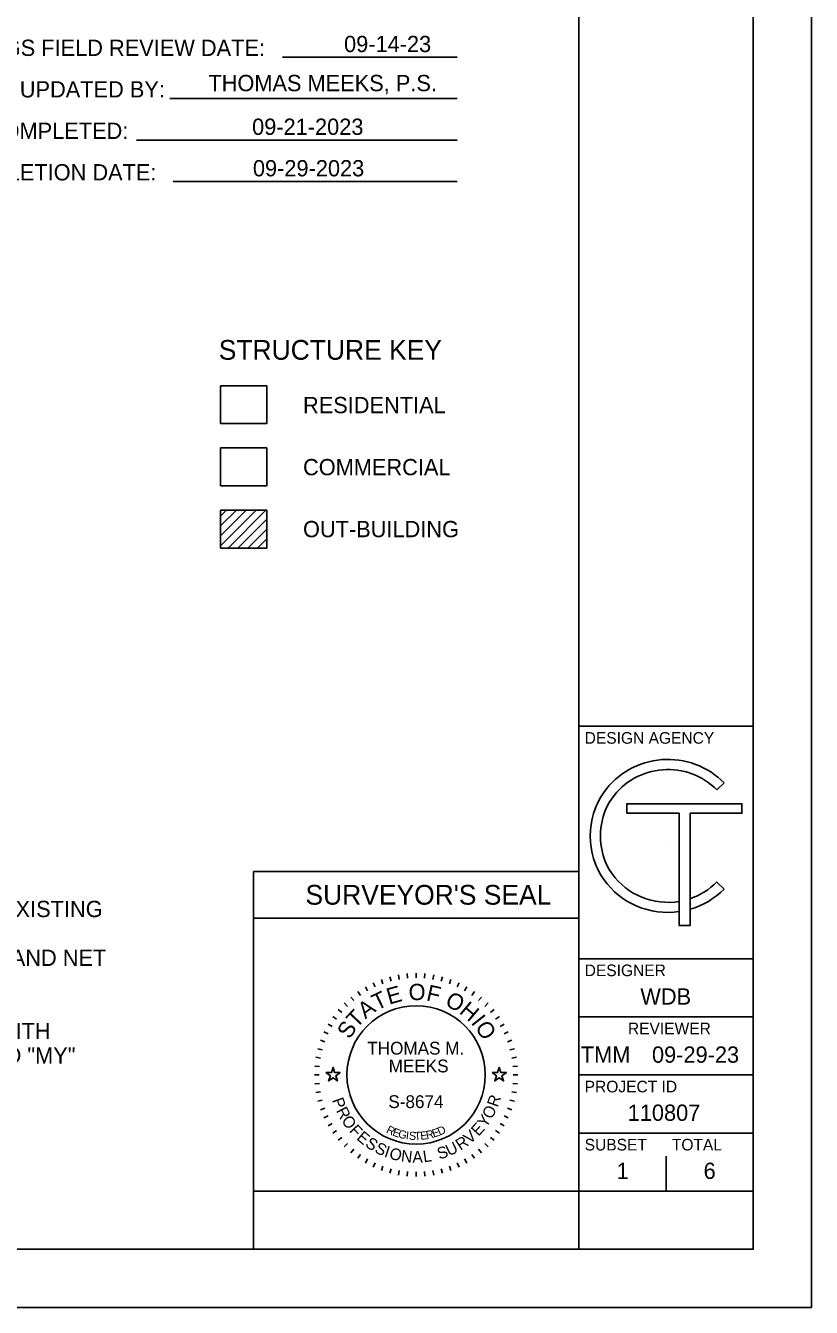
# Model space of a CAD drawing. Extents: x 0 to 34, y 0 to 22.
# Drawn here: x 27.24 to 34, y 0 to 11.03 of the extents above; entities that cross this region are included whole.
import ezdxf

# ---------------------------------------------------------------- set-up
doc = ezdxf.new("R2010")
doc.units = 0
for name, color, linetype in [('Default', 7, 'Continuous'), ('SC_Shading1', 7, 'Continuous'), ('SH_Border', 7, 'Continuous'), ('SH_Cut_Line', 7, 'Continuous'), ('SH_Data', 7, 'Continuous'), ('SH_Text', 7, 'Continuous')]:
    doc.layers.add(name, color=color, linetype=linetype)

msp = doc.modelspace()

# ---------------------------------------------------------------- linework, layer by layer
at = {"layer": 'Default'}
for points in [[(29.824, 2.02), (29.871, 2.02), (29.885, 2.065), (29.899, 2.02), (29.946, 2.02), (29.908, 1.992), (29.923, 1.948), (29.885, 1.975), (29.847, 1.948), (29.862, 1.992)], [(31.254, 2.02), (31.301, 2.02), (31.315, 2.065), (31.329, 2.02), (31.376, 2.02), (31.338, 1.992), (31.353, 1.948), (31.315, 1.975), (31.277, 1.948), (31.292, 1.992)]]:
    msp.add_lwpolyline(points, close=True, dxfattribs=at)
at = {"layer": 'SC_Shading1'}
msp.add_lwpolyline([(28.918, 7.069), (29.315, 7.069), (29.315, 7.395), (28.918, 7.395)], close=True, dxfattribs=at)
at = {"layer": 'SH_Border'}
for p, q in [((32, 0.5), (32, 21.5)), ((32, 5), (33.5, 5)), ((32, 3), (33.5, 3)), ((32, 2.5), (33.5, 2.5)), ((32, 2), (33.5, 2)), ((32, 1.5), (33.5, 1.5)), ((32, 1), (33.5, 1))]:
    msp.add_line(p, q, dxfattribs=at)
msp.add_lwpolyline([(1.5, 21.5), (33.5, 21.5), (33.5, 0.5), (1.5, 0.5)], close=True, dxfattribs=at)
at = {"layer": 'SH_Cut_Line'}
msp.add_lwpolyline([(0, 0), (34, 0), (34, 22), (0, 22)], close=True, dxfattribs=at)
at = {"layer": 'SH_Data'}
for p, q in [((32.75, 4), (32.75, 4)), ((32, 3.75), (29.2, 3.75)), ((29.2, 3.75), (29.2, 0.5)), ((32, 0.5), (32, 3.75)), ((32, 3.35), (29.2, 3.35)), ((30.524, 2.872), (30.527, 2.832)), ((30.6, 2.875), (30.6, 2.835)), ((30.676, 2.872), (30.673, 2.832)), ((30.163, 2.758), (30.183, 2.723)), ((30.23, 2.793), (30.247, 2.757)), ((30.301, 2.822), (30.314, 2.785)), ((30.374, 2.845), (30.384, 2.807)), ((30.448, 2.862), (30.455, 2.822)), ((30.752, 2.862), (30.745, 2.822)), ((30.826, 2.845), (30.816, 2.807)), ((30.899, 2.822), (30.886, 2.785)), ((30.97, 2.793), (30.953, 2.757)), ((31.037, 2.758), (31.017, 2.723)), ((30.038, 2.67), (30.063, 2.64)), ((30.098, 2.717), (30.121, 2.684)), ((31.102, 2.717), (31.079, 2.684)), ((31.162, 2.67), (31.137, 2.64)), ((29.93, 2.562), (29.96, 2.537)), ((29.981, 2.619), (30.01, 2.59)), ((31.219, 2.619), (31.19, 2.59)), ((31.27, 2.562), (31.24, 2.537)), ((29.842, 2.438), (29.877, 2.418)), ((29.883, 2.502), (29.916, 2.479)), ((31.317, 2.502), (31.284, 2.479)), ((31.358, 2.438), (31.323, 2.418)), ((29.807, 2.37), (29.843, 2.353)), ((31.393, 2.37), (31.357, 2.353)), ((29.755, 2.226), (29.793, 2.216)), ((29.778, 2.299), (29.815, 2.286)), ((31.422, 2.299), (31.385, 2.286)), ((31.445, 2.226), (31.407, 2.216)), ((29.738, 2.152), (29.778, 2.145)), ((31.462, 2.152), (31.422, 2.145)), ((29.725, 2), (29.765, 2)), ((29.728, 2.076), (29.768, 2.073)), ((31.472, 2.076), (31.432, 2.073)), ((31.475, 2), (31.435, 2)), ((29.728, 1.924), (29.768, 1.927)), ((31.472, 1.924), (31.432, 1.927)), ((29.738, 1.848), (29.778, 1.855)), ((29.755, 1.774), (29.793, 1.784)), ((31.445, 1.774), (31.407, 1.784)), ((31.462, 1.848), (31.422, 1.855)), ((29.778, 1.701), (29.815, 1.714)), ((31.422, 1.701), (31.385, 1.714)), ((29.807, 1.63), (29.843, 1.647)), ((29.842, 1.563), (29.877, 1.583)), ((31.358, 1.563), (31.323, 1.583)), ((31.393, 1.63), (31.357, 1.647)), ((29.883, 1.498), (29.916, 1.521)), ((29.93, 1.438), (29.96, 1.463)), ((31.27, 1.438), (31.24, 1.463)), ((31.317, 1.498), (31.284, 1.521)), ((29.981, 1.381), (30.01, 1.41)), ((30.038, 1.33), (30.063, 1.36)), ((31.162, 1.33), (31.137, 1.36)), ((31.219, 1.381), (31.19, 1.41)), ((30.098, 1.283), (30.121, 1.316)), ((30.163, 1.242), (30.183, 1.277)), ((30.23, 1.207), (30.247, 1.243)), ((30.301, 1.178), (30.314, 1.215)), ((30.899, 1.178), (30.886, 1.215)), ((30.97, 1.207), (30.953, 1.243)), ((31.037, 1.242), (31.017, 1.277)), ((31.102, 1.283), (31.079, 1.316)), ((32.75, 1), (32.75, 1.3)), ((30.374, 1.155), (30.384, 1.193)), ((30.448, 1.138), (30.455, 1.178)), ((30.524, 1.128), (30.527, 1.168)), ((30.6, 1.125), (30.6, 1.165)), ((30.676, 1.128), (30.673, 1.168)), ((30.752, 1.138), (30.745, 1.178)), ((30.826, 1.155), (30.816, 1.193)), ((32, 0.5), (29.2, 0.5))]:
    msp.add_line(p, q, dxfattribs=at)
msp.add_lwpolyline([(32, 0.5), (32, 1), (29.2, 1), (29.2, 0.5)], close=True, dxfattribs=at)
msp.add_circle((30.6, 2), 0.595, dxfattribs=at)
at = {"layer": 'SH_Text'}
for p, q in [((29.45, 10.758), (30.953, 10.758)), ((28.48, 10.401), (30.953, 10.401)), ((28.195, 10.044), (30.953, 10.044)), ((28.51, 9.687), (30.953, 9.687)), ((28.918, 6.858), (28.919, 6.86)), ((28.918, 6.808), (28.969, 6.86)), ((28.918, 6.724), (29.054, 6.86)), ((28.918, 6.639), (29.138, 6.86)), ((28.918, 6.554), (29.223, 6.86)), ((28.982, 6.534), (29.308, 6.86)), ((29.067, 6.534), (29.315, 6.782)), ((29.151, 6.534), (29.315, 6.697)), ((28.918, 6.538), (28.922, 6.534)), ((29.236, 6.534), (29.315, 6.612)), ((33.249, 4.513), (33.187, 4.452)), ((33.249, 4.513), (33.187, 4.452)), ((33.402, 4.333), (32.414, 4.333)), ((32.414, 4.333), (32.414, 4.251)), ((33.402, 4.251), (33.402, 4.333)), ((32.414, 4.251), (32.863, 4.251)), ((32.863, 4.251), (32.863, 3.285)), ((32.956, 3.285), (32.956, 4.251)), ((32.956, 4.251), (33.402, 4.251)), ((33.187, 3.66), (33.249, 3.599)), ((33.187, 3.66), (33.249, 3.599)), ((32.863, 3.493), (32.863, 3.405)), ((32.863, 3.493), (32.863, 3.405)), ((32.956, 3.425), (32.956, 3.516)), ((32.956, 3.425), (32.956, 3.516)), ((32.863, 3.285), (32.956, 3.285))]:
    msp.add_line(p, q, dxfattribs=at)
for points in [[(28.918, 7.93), (29.315, 7.93), (29.315, 7.605), (28.918, 7.605)], [(28.918, 6.86), (29.315, 6.86), (29.315, 6.534), (28.918, 6.534)], [(32.863, 4.251), (32.863, 3.285), (32.956, 3.285), (32.956, 4.251), (33.402, 4.251), (33.402, 4.333), (32.414, 4.333), (32.414, 4.251)]]:
    msp.add_lwpolyline(points, close=True, dxfattribs=at)
for centre, radius, start, end in [((32.766, 4.035), 0.68, 44.7027, 144.3276), ((32.766, 4.035), 0.68, 44.7027, 144.3276), ((32.766, 4.035), 0.593, 44.7362, 144.1102), ((32.766, 4.035), 0.593, 44.7362, 144.1102), ((32.764, 4.056), 0.666, 145.7329, 214.2671), ((32.764, 4.056), 0.666, 145.7329, 214.2671), ((32.764, 4.056), 0.579, 145.7266, 214.2734), ((32.764, 4.056), 0.579, 145.7266, 214.2734), ((32.766, 4.078), 0.68, 215.6724, 278.2613), ((32.766, 4.078), 0.68, 215.6724, 278.2613), ((32.766, 4.078), 0.593, 215.8898, 279.4882), ((32.766, 4.078), 0.593, 215.8898, 279.4882), ((32.766, 4.078), 0.593, 288.6992, 315.2638), ((32.766, 4.078), 0.593, 288.6992, 315.2638), ((32.766, 4.078), 0.68, 286.2291, 315.2973), ((32.766, 4.078), 0.68, 286.2291, 315.2973)]:
    msp.add_arc(centre, radius, start, end, dxfattribs=at)

# ---------------------------------------------------------------- texts
at = {"layer": 'Default'}
for s, p in [('09-14-23', (29.98, 10.801)), ('THOMAS MEEKS, P.S.', (28.813, 10.465)), ('09-21-2023', (29.189, 10.089)), ('09-29-2023', (29.196, 9.732))]:
    msp.add_text(s, height=0.14, dxfattribs=at).set_placement(p)
at = {"layer": 'SH_Data'}
for s, height, p in [('DESIGN AGENCY', 0.1, (32.05, 4.85)), ("SURVEYOR'S SEAL", 0.17, (29.648, 3.465)), ('I HAVE REESTABLISHED THE LOCATIONS OF THE EXISTING PROPERTY LINES, THE EXISTING CENTERLINE RIGHT OF WAY, AND THE EXISTING', 0.14, (14.869, 3.358)), ('ESTABLISHED THE PROPOSED PROPERTY LINES, CALCULATED THE GROSS TAKE, PRESENT ROADWAY OCCUPIED (PRO), NET TAKE AND NET', 0.14, (14.869, 2.938)), ('DESIGNER', 0.1, (32.05, 2.85)), ('WDB', 0.14, (32.529, 2.605)), ('DEPARTMENT OF TRANSPORTATION DATED 09-22-2010. ALL OF MY WORK CONTAINED HEREIN WAS CONDUCTED IN ACCORDANCE WITH', 0.14, (14.869, 2.308)), ('REVIEWER', 0.1, (32.422, 2.35)), ('THE OHIO ADMINISTRATIVE CODE CHAPTER 4733-37 STANDARDS FOR BOUNDARY SURVEYS, UNLESS SO NOTED. THE WORDS "I" AND "MY"', 0.14, (14.869, 2.098)), ('THOMAS M.', 0.11, (30.18, 2.175)), ('TMM', 0.14, (32.017, 2.105)), ('09-29-23', 0.14, (32.629, 2.105)), ('MEEKS', 0.11, (30.364, 2.022)), ('PROJECT ID', 0.1, (32.05, 1.85)), ('S-8674', 0.11, (30.361, 1.715)), ('110807', 0.14, (32.42, 1.605)), ('SUBSET', 0.1, (32.05, 1.35)), ('TOTAL', 0.1, (32.8, 1.35)), ('1', 0.14, (32.325, 1.105)), ('6', 0.14, (33.073, 1.105))]:
    msp.add_text(s, height=height, dxfattribs=at).set_placement(p)
for s, height, rotation, p in [('E', 0.14, 15.7571, (30.368, 2.604)), ('O', 0.14, 359.7812, (30.535, 2.644)), ('F', 0.14, 347.4362, (30.681, 2.642)), ('T', 0.14, 25.7167, (30.262, 2.552)), ('O', 0.14, 332.2586, (30.84, 2.602)), ('T', 0.14, 46.4344, (30.088, 2.396)), ('A', 0.14, 36.4747, (30.163, 2.478)), ('H', 0.14, 319.9136, (30.963, 2.536)), ('S', 0.14, 57.1924, (30.028, 2.301)), ('I', 0.14, 308.367, (31.066, 2.448)), ('O', 0.14, 303.1491, (31.102, 2.409)), ('P', 0.1, 289.7431, (29.875, 1.784)), ('R', 0.1, 70.983, (31.301, 1.717)), ('R', 0.1, 296.9802, (29.909, 1.693)), ('Y', 0.1, 55.5058, (31.2, 1.54)), ('O', 0.1, 62.7428, (31.25, 1.613)), ('O', 0.1, 304.7158, (29.953, 1.608)), ('F', 0.1, 312.956, (30.019, 1.516)), ('R', 0.07, 334.487, (30.337, 1.505)), ('D', 0.07, 23.3052, (30.801, 1.477)), ('E', 0.1, 48.2687, (31.137, 1.467)), ('E', 0.1, 319.6885, (30.081, 1.45)), ('S', 0.1, 326.9255, (30.155, 1.389)), ('E', 0.07, 341.04, (30.391, 1.48)), ('G', 0.07, 347.4752, (30.441, 1.462)), ('I', 0.07, 353.7858, (30.509, 1.447)), ('S', 0.07, 356.8926, (30.536, 1.443)), ('T', 0.07, 3.0061, (30.586, 1.439)), ('E', 0.07, 6.0117, (30.639, 1.441)), ('R', 0.07, 11.9184, (30.692, 1.447)), ('E', 0.07, 17.6836, (30.75, 1.46)), ('R', 0.1, 33.296, (30.981, 1.347)), ('V', 0.1, 41.0316, (31.061, 1.401)), ('S', 0.1, 334.1626, (30.236, 1.337)), ('I', 0.1, 341.3997, (30.319, 1.298)), ('O', 0.1, 345.1351, (30.362, 1.282)), ('N', 0.1, 353.3752, (30.466, 1.255)), ('A', 0.1, 1.1108, (30.569, 1.244)), ('L', 0.1, 8.3479, (30.666, 1.247)), ('S', 0.1, 18.3234, (30.8, 1.271)), ('U', 0.1, 25.5604, (30.883, 1.299))]:
    msp.add_text(s, height=height, rotation=rotation, dxfattribs=at).set_placement(p)
at = {"layer": 'SH_Text'}
for s, height, p in [('TRACINGS FIELD REVIEW DATE:', 0.14, (26.356, 10.768)), ('OWNERSHIP UPDATED BY:', 0.14, (25.984, 10.411)), ('DATE COMPLETED:', 0.14, (26.356, 10.054)), ('PLAN COMPLETION DATE:', 0.14, (25.984, 9.697)), ('STRUCTURE KEY', 0.17, (28.902, 8.154)), ('RESIDENTIAL', 0.14, (29.627, 7.694)), ('COMMERCIAL', 0.14, (29.627, 7.16)), ('OUT-BUILDING', 0.14, (29.627, 6.627))]:
    msp.add_text(s, height=height, dxfattribs=at).set_placement(p)

doc.saveas('drawing.dxf')
